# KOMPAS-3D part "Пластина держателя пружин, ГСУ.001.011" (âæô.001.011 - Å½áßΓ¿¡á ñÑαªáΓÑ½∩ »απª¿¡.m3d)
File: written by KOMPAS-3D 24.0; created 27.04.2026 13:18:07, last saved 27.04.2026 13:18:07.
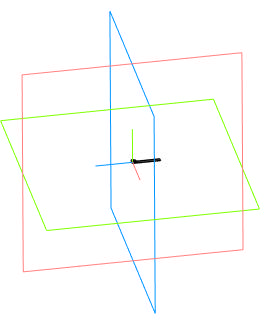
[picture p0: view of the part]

Document properties: Автор: User7; Полное имя файла: C:\Users\User7\Desktop\олимп\ГСУ.001.011 - Пластина держателя пружин.m3d

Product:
- Part/product: Пластина держателя пружин  | designation ГСУ.001.011
    Масса: 0.000005

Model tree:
1. Эскиз:1
2. Листовое тело:1
     Расстояние 1 = 10; Толщина листового тела = 0.1; Радиус сгиба = 5
3. Сгиб:1  (with: Ребро.Листовое тело:1)
     Радиус сгиба = 0.2; Коэффициент = 0.4; Величина сгиба = 10; Радиус сгиба = 0.2; Толщина листового тела = 0.1; Угол сгиба = 199; Ширина освобождения сгиба = 3; Ширина сгиба = 0.8; Длина 1 = 1.12; Длина 2 = 10

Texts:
  ГСУ.001.011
